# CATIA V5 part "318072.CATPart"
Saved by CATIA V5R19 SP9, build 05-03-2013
Part number: 318072
Source: Unknown
Bounding box of the stored display mesh (mm): x -177.21 to -16.958, y -224.995 to -186.198, z 466.826 to 488.593
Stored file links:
  D:\16-SIL\kale oto\R19_V1\318072.CATPart
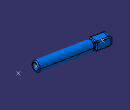
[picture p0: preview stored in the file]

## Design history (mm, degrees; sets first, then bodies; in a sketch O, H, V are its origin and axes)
Set1
  Point1 to Point3: stored without definition
Body1 "241\\233\\231\\MANIFOLD_SOLID_BREP #158715" (main body)
  Solid1: solid without history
